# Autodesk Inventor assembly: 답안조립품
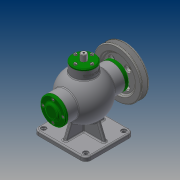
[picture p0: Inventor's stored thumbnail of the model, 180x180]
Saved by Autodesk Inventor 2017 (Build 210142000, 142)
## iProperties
Part Number: 답안조립품
Material: 일반
Document SubType Name: Assembly
Designer: 13
Author: 13
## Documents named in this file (19)
- C:\Users\13\Desktop\480414V1002\답안조립품.iam
- C:\Users\13\Desktop\480414V1002\본체.ipt
- C:\Users\13\Desktop\480414V1002\뒤커버.ipt
- C:\Users\13\Desktop\480414V1002\앞커버.ipt
- C:\Users\13\Desktop\480414V1002\오일 실 15 30 7.ipt
- C:\Users\13\Desktop\480414V1002\베어링 6202.ipt
- 베어링 6202.ipt
- C:\Users\13\Desktop\480414V1002\멈춤링 15x1.ipt
- C:\Users\13\Desktop\480414V1002\편심축.ipt
- C:\Users\13\Desktop\480414V1002\부시.ipt
- C:\Users\13\Desktop\480414V1002\멈춤링 35x1.6.ipt
- 멈춤링 35x1.6.ipt
- C:\Users\13\Desktop\480414V1002\키 4x4x12.ipt
- C:\Users\13\Desktop\480414V1002\V-벨트풀리.ipt
- C:\Users\13\Desktop\480414V1002\너트 M8.ipt
- C:\Users\13\Desktop\480414V1002\상부커버.ipt
- C:\Users\13\Desktop\480414V1002\볼트 M4x16.ipt
- C:\Users\13\Desktop\480414V1002\볼트 M4x12.ipt
- C:\Users\13\Desktop\480414V1002\슬라이드.ipt
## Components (1 placed, 1 different names)
1. V-벨트풀리:1 — 플러쉬:1
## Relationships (1: Flush 1)
- 플러쉬:1 [Flush]: V-벨트풀리:1
